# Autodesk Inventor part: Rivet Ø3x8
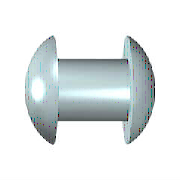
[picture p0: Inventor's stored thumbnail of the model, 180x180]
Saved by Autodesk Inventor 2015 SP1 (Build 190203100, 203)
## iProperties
Created: 2011-02
Part Number: Rivet Ø3x8
Material: Steel, Mild
Description: ISO/R 1051 - 3 x 8
Document SubType Name: Modeling
Standard: ISO 1051
Designer: Guilherme Augusto Franco de Souza
Standard Revision: First edition 1999-12-01
Standards Organization: ISO
Language: en-US
Size Designation: 3 x 8
Categories: <MemberInstance><Categories><Category DisplayName="Fasteners" InternalName="e4da775c-781d-43d5-af7c-5136215cf5a6" Mnemonic="FSTN"><Category DisplayName="Rivets"
Density: 1 g/cm^3
Appearance: Steel
IsCustomPart: 1
Author: Guilherme Augusto Franco de Souza
Revision Number: 00
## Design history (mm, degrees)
sketch "Sketch"
  geometry: L1 (0, 1.5)-(3.501, 1.5); L2 (3.501, 1.5)-(3.501, 2.6); L3 (0, 1.5)-(0, 2.6); L4 (-1.8, 0)-(5.301, 0); L5 (-4.82, 0)-(8.321, 0) reference; L6 (0, -0.774)-(0, 4.646) reference; A1 r 2.778 centre (0.978, 0) between (0, 2.6) and (-1.8, 0); A2 r 2.778 centre (2.523, 0) between (5.301, 0) and (3.501, 2.6)
  constraints: 8 end point, 5 point on circle, 4 point on line, 2 centre point, 2 collinear, 2 perpendicular, 1 horizontal, 1 parallel
  dimensions: "d0" = 3 diameter of L1 L4 (= NND1); "d1" = 3.501 distance of L1.start L1.end (computed from KLG); "d2" = 5.2 diameter of L3.end L4 (= KOD); "d3" = 1.8 horizontal distance of L4.start L3.end (= KOH); "d4" = 5.2 diameter of L2.end L4 (= KOD1); "d5" = 1.8 horizontal distance of L4.end L2.end (= KOH1)
revolve "Body" sketch "Sketch" stored, may be unused: angle "d11" = 90 deg
body "Solid1"
other parameters: "KOH" = 1.8 [user parameter; used in 2 equation terms], "KOH1" = 1.8 (= KOH) [user parameter; used in 1 equation term], "KOD" = 5.2 [user parameter; used in 2 equation terms], "KOD1" = 5.2 (= KOD) [user parameter; used in 1 equation term], "NND1" = 3 (= NND) [user parameter; used in 1 equation term], "KLG" = 3.5 [user parameter; used in 1 equation term], "d7" = 0, "d15" = 0, "d16" = 0, "NLG" = 8 [user parameter], "KLGMIN" = 0.001 [user parameter], "NND" = 3 [user parameter; used in 1 equation term], "KLGMAX" = 4 [user parameter]
